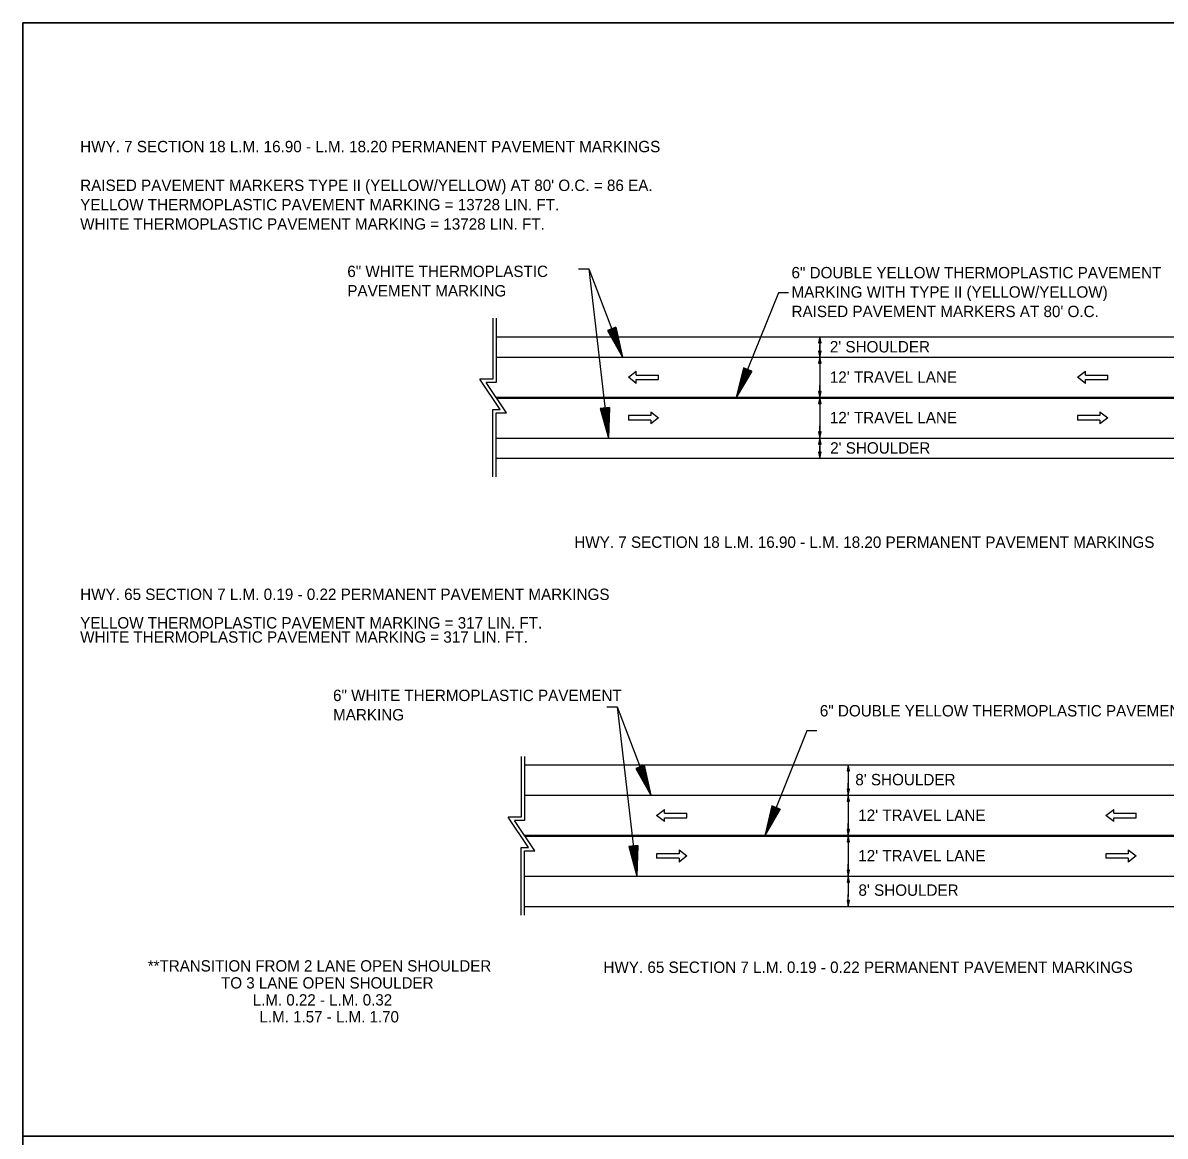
# Model space of a CAD drawing. Extents: x 1373096 to 1373266, y 381130 to 381790.
# Drawn here: x 1373096 to 1373208.9, y 381680.2 to 381790.2 of the extents above; entities that cross this region are included whole.
import ezdxf

# ---------------------------------------------------------------- set-up
doc = ezdxf.new("R2010")
doc.units = 0
for name, color, linetype in [('Default', 7, 'Continuous'), ('DSN_DRFT_Junk-No-Plot', 7, 'Continuous'), ('R_Draft', 7, 'Continuous'), ('SHET_Border-Text', 7, 'Continuous')]:
    doc.layers.add(name, color=color, linetype=linetype)

msp = doc.modelspace()

# ---------------------------------------------------------------- linework, layer by layer
at = {"layer": 'Default'}
for p, q in [((1373150.91, 381765.87), (1373151.91, 381765.87)), ((1373151.91, 381765.87), (1373155.26, 381757.15)), ((1373151.91, 381765.87), (1373153.86, 381749.15)), ((1373170.66, 381763.5), (1373166.5, 381753.15)), ((1373171.66, 381763.5), (1373170.66, 381763.5)), ((1373142.44, 381760.98), (1373142.44, 381754.98)), ((1373142.78, 381760.98), (1373142.78, 381754.65)), ((1373154.6, 381760.11), (1373153.76, 381759.79)), ((1373153.76, 381759.79), (1373155.26, 381757.15)), ((1373153.83, 381759.81), (1373155.08, 381757.62)), ((1373153.9, 381759.84), (1373154.89, 381758.1)), ((1373153.97, 381759.87), (1373154.71, 381758.56)), ((1373154.05, 381759.9), (1373154.53, 381759.04)), ((1373154.12, 381759.92), (1373154.35, 381759.51)), ((1373154.25, 381759.97), (1373154.35, 381759.51)), ((1373154.32, 381760), (1373154.53, 381759.04)), ((1373154.39, 381760.03), (1373154.71, 381758.56)), ((1373154.46, 381760.06), (1373154.89, 381758.1)), ((1373154.53, 381760.08), (1373155.08, 381757.62)), ((1373154.6, 381760.11), (1373155.26, 381757.15)), ((1373167.2, 381756.1), (1373166.5, 381753.15)), ((1373167.27, 381756.07), (1373166.69, 381753.61)), ((1373167.34, 381756.04), (1373166.88, 381754.09)), ((1373167.41, 381756.02), (1373167.07, 381754.56)), ((1373168.04, 381755.76), (1373167.2, 381756.1)), ((1373167.48, 381755.99), (1373167.26, 381755.03)), ((1373167.75, 381755.88), (1373167.26, 381755.03)), ((1373167.55, 381755.96), (1373167.44, 381755.49)), ((1373167.68, 381755.91), (1373167.44, 381755.49)), ((1373143.16, 381751.98), (1373141.16, 381754.98)), ((1373142.44, 381754.98), (1373141.16, 381754.98)), ((1373155.83, 381755.15), (1373156.61, 381755.75)), ((1373156.61, 381754.55), (1373155.83, 381755.15)), ((1373156.61, 381755.37), (1373156.61, 381755.75)), ((1373156.61, 381755.37), (1373158.81, 381755.37)), ((1373156.61, 381754.92), (1373158.81, 381754.92)), ((1373156.61, 381754.55), (1373156.61, 381754.92)), ((1373158.81, 381754.92), (1373158.81, 381755.37)), ((1373168.04, 381755.76), (1373166.5, 381753.15)), ((1373167.97, 381755.79), (1373166.69, 381753.61)), ((1373167.9, 381755.82), (1373166.88, 381754.09)), ((1373167.83, 381755.85), (1373167.07, 381754.56)), ((1373200.24, 381755.15), (1373201.02, 381755.75)), ((1373201.02, 381754.55), (1373200.24, 381755.15)), ((1373201.02, 381755.37), (1373201.02, 381755.75)), ((1373201.02, 381755.37), (1373203.23, 381755.37)), ((1373201.02, 381754.92), (1373203.23, 381754.92)), ((1373201.02, 381754.55), (1373201.02, 381754.92)), ((1373203.23, 381754.92), (1373203.23, 381755.37)), ((1373142.78, 381754.65), (1373141.78, 381754.65)), ((1373143.78, 381751.65), (1373141.78, 381754.65)), ((1373142.44, 381751.98), (1373143.16, 381751.98)), ((1373142.44, 381745.31), (1373142.44, 381751.98)), ((1373142.78, 381745.31), (1373142.78, 381751.65)), ((1373142.78, 381751.65), (1373143.78, 381751.65)), ((1373153.96, 381752.18), (1373153.06, 381752.08)), ((1373153.06, 381752.08), (1373153.86, 381749.15)), ((1373153.14, 381752.08), (1373153.8, 381749.65)), ((1373153.21, 381752.09), (1373153.74, 381750.16)), ((1373153.29, 381752.1), (1373153.68, 381750.65)), ((1373153.36, 381752.11), (1373153.62, 381751.16)), ((1373153.44, 381752.12), (1373153.56, 381751.66)), ((1373153.58, 381752.14), (1373153.56, 381751.66)), ((1373153.65, 381752.14), (1373153.62, 381751.16)), ((1373153.73, 381752.15), (1373153.68, 381750.65)), ((1373153.81, 381752.16), (1373153.74, 381750.16)), ((1373153.88, 381752.17), (1373153.8, 381749.65)), ((1373153.96, 381752.18), (1373153.86, 381749.15)), ((1373158.04, 381751.37), (1373155.83, 381751.37)), ((1373155.83, 381751.37), (1373155.83, 381750.92)), ((1373158.04, 381751.75), (1373158.04, 381751.37)), ((1373158.04, 381751.75), (1373158.81, 381751.15)), ((1373202.45, 381751.37), (1373200.24, 381751.37)), ((1373200.24, 381751.37), (1373200.24, 381750.92)), ((1373202.45, 381751.75), (1373202.45, 381751.37)), ((1373202.45, 381751.75), (1373203.23, 381751.15)), ((1373158.04, 381750.92), (1373155.83, 381750.92)), ((1373158.81, 381751.15), (1373158.04, 381750.55)), ((1373158.04, 381750.92), (1373158.04, 381750.55)), ((1373202.45, 381750.92), (1373200.24, 381750.92)), ((1373203.23, 381751.15), (1373202.45, 381750.55)), ((1373202.45, 381750.92), (1373202.45, 381750.55)), ((1373153.71, 381722.58), (1373154.71, 381722.58)), ((1373154.71, 381722.58), (1373158.06, 381713.86)), ((1373154.71, 381722.58), (1373156.66, 381705.86)), ((1373173.46, 381720.21), (1373169.31, 381709.86)), ((1373174.46, 381720.21), (1373173.46, 381720.21)), ((1373145.25, 381717.7), (1373145.25, 381711.69)), ((1373145.58, 381717.7), (1373145.58, 381711.36)), ((1373157.41, 381716.82), (1373156.57, 381716.5)), ((1373156.57, 381716.5), (1373158.06, 381713.86)), ((1373156.64, 381716.52), (1373157.88, 381714.33)), ((1373156.71, 381716.55), (1373157.7, 381714.81)), ((1373156.78, 381716.58), (1373157.52, 381715.27)), ((1373156.85, 381716.61), (1373157.34, 381715.75)), ((1373156.92, 381716.63), (1373157.16, 381716.22)), ((1373157.05, 381716.68), (1373157.16, 381716.22)), ((1373157.12, 381716.71), (1373157.34, 381715.75)), ((1373157.2, 381716.74), (1373157.52, 381715.27)), ((1373157.27, 381716.77), (1373157.7, 381714.81)), ((1373157.34, 381716.79), (1373157.88, 381714.33)), ((1373157.41, 381716.82), (1373158.06, 381713.86)), ((1373158.63, 381711.86), (1373159.41, 381712.46)), ((1373159.41, 381711.26), (1373158.63, 381711.86)), ((1373159.41, 381712.08), (1373159.41, 381712.46)), ((1373159.41, 381712.08), (1373161.62, 381712.08)), ((1373161.62, 381711.63), (1373161.62, 381712.08)), ((1373170.01, 381712.81), (1373169.31, 381709.86)), ((1373170.84, 381712.47), (1373169.31, 381709.86)), ((1373170.07, 381712.78), (1373169.49, 381710.32)), ((1373170.77, 381712.5), (1373169.49, 381710.32)), ((1373170.15, 381712.75), (1373169.68, 381710.8)), ((1373170.7, 381712.53), (1373169.68, 381710.8)), ((1373170.22, 381712.73), (1373169.87, 381711.27)), ((1373170.63, 381712.56), (1373169.87, 381711.27)), ((1373170.84, 381712.47), (1373170.01, 381712.81)), ((1373170.29, 381712.7), (1373170.06, 381711.74)), ((1373170.56, 381712.59), (1373170.06, 381711.74)), ((1373170.36, 381712.67), (1373170.25, 381712.2)), ((1373170.49, 381712.62), (1373170.25, 381712.2)), ((1373203.05, 381711.86), (1373203.82, 381712.46)), ((1373203.82, 381711.26), (1373203.05, 381711.86)), ((1373203.82, 381712.08), (1373203.82, 381712.46)), ((1373203.82, 381712.08), (1373206.03, 381712.08)), ((1373206.03, 381711.63), (1373206.03, 381712.08)), ((1373145.96, 381708.69), (1373143.96, 381711.69)), ((1373145.25, 381711.69), (1373143.96, 381711.69)), ((1373145.58, 381711.36), (1373144.58, 381711.36)), ((1373146.58, 381708.36), (1373144.58, 381711.36)), ((1373159.41, 381711.63), (1373161.62, 381711.63)), ((1373159.41, 381711.26), (1373159.41, 381711.63)), ((1373203.82, 381711.63), (1373206.03, 381711.63)), ((1373203.82, 381711.26), (1373203.82, 381711.63)), ((1373145.25, 381708.69), (1373145.96, 381708.69)), ((1373145.25, 381702.02), (1373145.25, 381708.69)), ((1373156.76, 381708.89), (1373155.87, 381708.79)), ((1373155.87, 381708.79), (1373156.66, 381705.86)), ((1373155.94, 381708.8), (1373156.6, 381706.36)), ((1373156.02, 381708.8), (1373156.54, 381706.87)), ((1373156.09, 381708.81), (1373156.48, 381707.36)), ((1373156.17, 381708.82), (1373156.43, 381707.87)), ((1373156.24, 381708.83), (1373156.37, 381708.37)), ((1373156.38, 381708.85), (1373156.37, 381708.37)), ((1373156.46, 381708.86), (1373156.43, 381707.87)), ((1373156.53, 381708.86), (1373156.48, 381707.36)), ((1373156.61, 381708.87), (1373156.54, 381706.87)), ((1373156.68, 381708.88), (1373156.6, 381706.36)), ((1373156.76, 381708.89), (1373156.66, 381705.86)), ((1373160.84, 381708.46), (1373160.84, 381708.08)), ((1373160.84, 381708.46), (1373161.62, 381707.86)), ((1373205.25, 381708.46), (1373205.25, 381708.08)), ((1373205.25, 381708.46), (1373206.03, 381707.86)), ((1373145.58, 381702.02), (1373145.58, 381708.36)), ((1373145.58, 381708.36), (1373146.58, 381708.36)), ((1373160.84, 381708.08), (1373158.63, 381708.08)), ((1373158.63, 381708.08), (1373158.63, 381707.63)), ((1373160.84, 381707.63), (1373158.63, 381707.63)), ((1373161.62, 381707.86), (1373160.84, 381707.26)), ((1373160.84, 381707.63), (1373160.84, 381707.26)), ((1373205.25, 381708.08), (1373203.05, 381708.08)), ((1373203.05, 381708.08), (1373203.05, 381707.63)), ((1373205.25, 381707.63), (1373203.05, 381707.63)), ((1373206.03, 381707.86), (1373205.25, 381707.26)), ((1373205.25, 381707.63), (1373205.25, 381707.26))]:
    msp.add_line(p, q, dxfattribs=at)
for points in [[(1373095.97, 381790.17), (1373095.97, 381680.17), (1373265.97, 381680.17), (1373265.97, 381790.17)], [(1373095.97, 381680.17), (1373095.97, 381570.17), (1373265.97, 381570.17), (1373265.97, 381680.17)], [(1373095.97, 381680.17), (1373095.97, 381570.17), (1373265.97, 381570.17), (1373265.97, 381680.17)]]:
    msp.add_lwpolyline(points, close=True, dxfattribs=at)
at = {"layer": 'DSN_DRFT_Junk-No-Plot'}
for p, q in [((1373174.76, 381759.15), (1373174.76, 381747.15)), ((1373177.57, 381715.86), (1373177.57, 381703.86))]:
    msp.add_line(p, q, dxfattribs=at)
for points in [[(1373095.97, 381790.17), (1373265.97, 381790.17), (1373265.97, 381680.17), (1373095.97, 381680.17)], [(1373095.97, 381790.17), (1373095.97, 381680.17), (1373265.97, 381680.17), (1373265.97, 381790.17)], [(1373095.97, 381680.17), (1373265.97, 381680.17), (1373265.97, 381570.17), (1373095.97, 381570.17)], [(1373095.97, 381680.17), (1373095.97, 381570.17), (1373265.97, 381570.17), (1373265.97, 381680.17)]]:
    msp.add_lwpolyline(points, close=True, dxfattribs=at)
for points in [[(1373174.76, 381759.15), (1373174.64, 381758.55), (1373174.88, 381758.55), (1373174.76, 381759.15), (1373174.76, 381757.95)], [(1373174.76, 381757.15), (1373174.88, 381757.75), (1373174.64, 381757.75), (1373174.76, 381757.15), (1373174.76, 381758.35)], [(1373174.76, 381757.15), (1373174.64, 381756.55), (1373174.88, 381756.55), (1373174.76, 381757.15), (1373174.76, 381755.95)], [(1373174.76, 381753.15), (1373174.88, 381753.75), (1373174.64, 381753.75), (1373174.76, 381753.15), (1373174.76, 381754.35)], [(1373174.76, 381753.15), (1373174.64, 381752.55), (1373174.88, 381752.55), (1373174.76, 381753.15), (1373174.76, 381751.95)], [(1373174.76, 381749.15), (1373174.88, 381749.75), (1373174.64, 381749.75), (1373174.76, 381749.15), (1373174.76, 381750.35)], [(1373174.76, 381749.15), (1373174.64, 381748.55), (1373174.88, 381748.55), (1373174.76, 381749.15), (1373174.76, 381747.95)], [(1373174.76, 381747.15), (1373174.88, 381747.75), (1373174.64, 381747.75), (1373174.76, 381747.15), (1373174.76, 381748.35)], [(1373177.57, 381716.87), (1373177.45, 381716.27), (1373177.69, 381716.27), (1373177.57, 381716.87), (1373177.57, 381715.67)], [(1373177.57, 381713.86), (1373177.69, 381714.46), (1373177.45, 381714.46), (1373177.57, 381713.86), (1373177.57, 381715.06)], [(1373177.57, 381713.86), (1373177.45, 381713.26), (1373177.69, 381713.26), (1373177.57, 381713.86), (1373177.57, 381712.66)], [(1373177.57, 381709.86), (1373177.69, 381710.46), (1373177.45, 381710.46), (1373177.57, 381709.86), (1373177.57, 381711.06)], [(1373177.57, 381709.86), (1373177.45, 381709.26), (1373177.69, 381709.26), (1373177.57, 381709.86), (1373177.57, 381708.66)], [(1373177.57, 381705.86), (1373177.69, 381706.46), (1373177.45, 381706.46), (1373177.57, 381705.86), (1373177.57, 381707.06)], [(1373177.57, 381705.86), (1373177.45, 381705.26), (1373177.69, 381705.26), (1373177.57, 381705.86), (1373177.57, 381704.66)], [(1373177.57, 381702.85), (1373177.69, 381703.45), (1373177.45, 381703.45), (1373177.57, 381702.85), (1373177.57, 381704.05)]]:
    msp.add_lwpolyline(points, dxfattribs=at)
at = {"layer": 'R_Draft'}
for p, q in [((1373142.78, 381759.15), (1373219.17, 381759.15)), ((1373142.78, 381757.15), (1373219.17, 381757.15)), ((1373142.74, 381753.2), (1373219.14, 381753.2)), ((1373142.81, 381753.1), (1373219.2, 381753.1)), ((1373142.78, 381749.15), (1373219.17, 381749.15)), ((1373142.78, 381747.15), (1373219.17, 381747.15)), ((1373145.58, 381716.86), (1373221.97, 381716.86)), ((1373145.58, 381713.86), (1373221.97, 381713.86)), ((1373145.55, 381709.91), (1373221.94, 381709.91)), ((1373145.62, 381709.81), (1373222.01, 381709.81)), ((1373145.58, 381705.86), (1373221.97, 381705.86)), ((1373145.58, 381702.86), (1373221.97, 381702.86))]:
    msp.add_line(p, q, dxfattribs=at)

# ---------------------------------------------------------------- texts
at = {"layer": 'Default'}
for s, p in [('HWY. 7 SECTION 18 L.M. 16.90 - L.M. 18.20 PERMANENT PAVEMENT MARKINGS', (1373101.64, 381777.39)), ("RAISED PAVEMENT MARKERS TYPE II (YELLOW/YELLOW) AT 80' O.C. = 86 EA.", (1373101.64, 381773.56)), ('YELLOW THERMOPLASTIC PAVEMENT MARKING = 13728 LIN. FT.', (1373101.64, 381771.65)), ('WHITE THERMOPLASTIC PAVEMENT MARKING = 13728 LIN. FT.', (1373101.64, 381769.74)), ('6" WHITE THERMOPLASTIC', (1373128.05, 381765.06)), ('6" DOUBLE YELLOW THERMOPLASTIC PAVEMENT', (1373171.96, 381764.93)), ('PAVEMENT MARKING', (1373128.05, 381763.14)), ('MARKING WITH TYPE II (YELLOW/YELLOW)', (1373171.96, 381763.02)), ("RAISED PAVEMENT MARKERS AT 80' O.C.", (1373171.96, 381761.1)), ('HWY. 65 SECTION 7 L.M. 0.19 - 0.22 PERMANENT PAVEMENT MARKINGS', (1373101.64, 381733.15)), ('YELLOW THERMOPLASTIC PAVEMENT MARKING = 317 LIN. FT.', (1373101.64, 381730.33)), ('WHITE THERMOPLASTIC PAVEMENT MARKING = 317 LIN. FT.', (1373101.64, 381728.93)), ('6" WHITE THERMOPLASTIC PAVEMENT ', (1373126.64, 381723.16)), ('MARKING ', (1373126.64, 381721.25)), ('6" DOUBLE YELLOW THERMOPLASTIC PAVEMENT MARKING', (1373174.76, 381721.64))]:
    msp.add_text(s, height=1.125, dxfattribs=at).set_placement(p)
at = {"layer": 'R_Draft'}
for s, p in [("2' SHOULDER", (1373175.75, 381757.61)), ("12' TRAVEL LANE", (1373175.75, 381754.61)), ("12' TRAVEL LANE", (1373175.75, 381750.61)), ("2' SHOULDER", (1373175.78, 381747.61)), ('HWY. 7 SECTION 18 L.M. 16.90 - L.M. 18.20 PERMANENT PAVEMENT MARKINGS', (1373150.49, 381738.3)), ("8' SHOULDER", (1373178.27, 381714.84)), ("12' TRAVEL LANE", (1373178.56, 381711.32)), ("12' TRAVEL LANE", (1373178.56, 381707.32)), ("8' SHOULDER", (1373178.58, 381703.92)), ('HWY. 65 SECTION 7 L.M. 0.19 - 0.22 PERMANENT PAVEMENT MARKINGS', (1373153.37, 381696.3))]:
    msp.add_text(s, height=1.125, dxfattribs=at).set_placement(p)
at = {"layer": 'SHET_Border-Text'}
for s, p in [('**TRANSITION FROM 2 LANE OPEN SHOULDER', (1373108.33, 381696.44)), ('TO 3 LANE OPEN SHOULDER', (1373115.57, 381694.76)), ('L.M. 0.22 - L.M. 0.32', (1373118.7, 381693.08)), ('L.M. 1.57 - L.M. 1.70', (1373119.37, 381691.41))]:
    msp.add_text(s, height=1.117, dxfattribs=at).set_placement(p)

doc.saveas('drawing.dxf')
